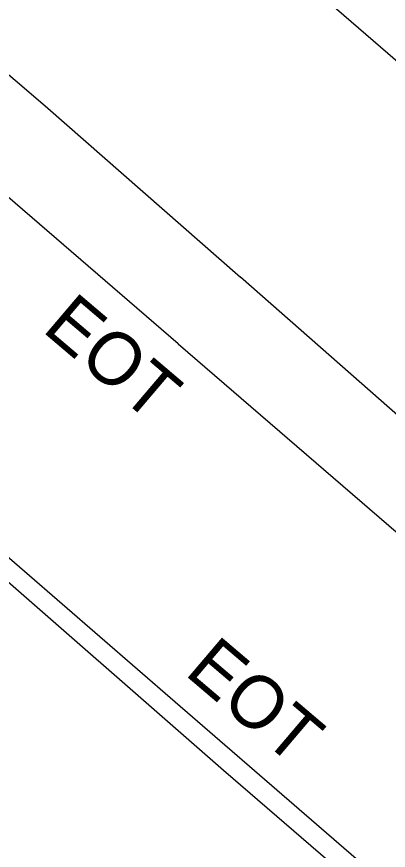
# Model space of a CAD drawing. Extents: x 2076109 to 2080761, y 592812 to 596750.
# Drawn here: x 2076795.1 to 2076830.5, y 596247.5 to 596326.7 of the extents above; entities that cross this region are included whole.
import ezdxf

# ---------------------------------------------------------------- set-up
doc = ezdxf.new("R2010")
doc.units = 0
for name, color, linetype in [('RD_EX_Fence_ChLk', 7, 'Continuous'), ('RD_EX_Misc', 7, 'Continuous'), ('RD_EX_Misc_txCode', 7, 'Continuous'), ('RD_EX_Road', 7, 'Continuous')]:
    doc.layers.add(name, color=color, linetype=linetype)

msp = doc.modelspace()

# ---------------------------------------------------------------- linework, layer by layer
at = {"layer": 'RD_EX_Fence_ChLk'}
msp.add_lwpolyline([(2076822.972, 596329.732), (2076907.019, 596257.073), (2076948.272, 596221.629), (2077023.379, 596156.571), (2077092.731, 596094.038)], dxfattribs=at)
msp.add_lwpolyline([(2076822.972, 596329.732), (2076907.019, 596257.073), (2076948.272, 596221.629), (2077023.379, 596156.571), (2077092.731, 596094.038)], dxfattribs=at)
at = {"layer": 'RD_EX_Misc'}
for points in [[(2076810.466, 596295.642), (2076777.154, 596324.358), (2076741.647, 596354.967), (2076702.034, 596388.717), (2076677.401, 596409.971), (2076647.315, 596435.894), (2076621.027, 596458.583), (2076590.117, 596485.04), (2076559.728, 596511.073), (2076528.183, 596538.3), (2076511.922, 596552.279), (2076473.053, 596585.805), (2076454.386, 596601.838), (2076432.84, 596620.26), (2076409.879, 596640.05), (2076391.022, 596656.418), (2076366.246, 596677.712), (2076342.594, 596698.155), (2076317.697, 596719.663), (2076298.567, 596736.157), (2076283.823, 596748.946)], [(2076810.466, 596295.642), (2076861.804, 596251.392), (2076900.569, 596218.064), (2076940.756, 596183.48), (2076983.389, 596147.001), (2077038.073, 596099.907), (2077086.972, 596057.778), (2077132.275, 596018.797), (2077181.847, 595976.05), (2077229.693, 595934.908), (2077274.19, 595896.66), (2077329.202, 595849.517), (2077358.599, 595824.219)], [(2076810.466, 596295.642), (2076861.804, 596251.392), (2076900.569, 596218.064), (2076940.756, 596183.48), (2076983.389, 596147.001), (2077038.073, 596099.907), (2077086.972, 596057.778), (2077132.275, 596018.797), (2077181.847, 595976.05), (2077229.693, 595934.908), (2077274.19, 595896.66), (2077329.202, 595849.517), (2077358.599, 595824.219)], [(2077334.925, 595810.962), (2077327.547, 595817.304), (2077300.531, 595840.367), (2077267.756, 595868.372), (2077240.066, 595892.053), (2077211.409, 595916.603), (2077178.431, 595944.966), (2077142.263, 595976.086), (2077108.469, 596005.28), (2077069.235, 596038.869), (2077039.155, 596064.675), (2077006.349, 596092.753), (2076967.206, 596126.449), (2076935.593, 596153.651), (2076905.142, 596179.726), (2076872.007, 596208.175), (2076841.3, 596234.653), (2076810.183, 596261.571), (2076792.251, 596277.094)], [(2077334.925, 595810.962), (2077327.547, 595817.304), (2077300.531, 595840.367), (2077267.756, 595868.372), (2077240.066, 595892.053), (2077211.409, 595916.603), (2077178.431, 595944.966), (2077142.263, 595976.086), (2077108.469, 596005.28), (2077069.235, 596038.869), (2077039.155, 596064.675), (2077006.349, 596092.753), (2076967.206, 596126.449), (2076935.593, 596153.651), (2076905.142, 596179.726), (2076872.007, 596208.175), (2076841.3, 596234.653), (2076810.183, 596261.571), (2076792.251, 596277.094)]]:
    msp.add_lwpolyline(points, dxfattribs=at)
at = {"layer": 'RD_EX_Road'}
for points in [[(2076295.807, 596750.034), (2076327.331, 596722.936), (2076360.431, 596694.098), (2076392.102, 596666.863), (2076422.239, 596640.73), (2076455.241, 596612.561), (2076486.01, 596586.14), (2076511.218, 596564.367), (2076545.634, 596535.19), (2076573.693, 596510.932), (2076594.173, 596493.793), (2076616.524, 596474.152), (2076639.677, 596454.591), (2076664.735, 596432.372), (2076686.112, 596413.804), (2076717.685, 596386.955), (2076745.584, 596362.767), (2076775.649, 596337.235), (2076797.834, 596318.25), (2076816.414, 596301.987)], [(2077309.592, 595877.223), (2077282.743, 595900.374), (2077256.364, 595923.264), (2077227.255, 595948.475), (2077198.785, 595972.866), (2077175.799, 595992.64), (2077153.365, 596012.36), (2077130.636, 596031.731), (2077105.618, 596053.51), (2077080.494, 596075.056), (2077051.539, 596099.906), (2077024.399, 596123.257), (2077002.193, 596142.322), (2076978.911, 596162.671), (2076952.209, 596185.236), (2076929.194, 596204.759), (2076902.686, 596227.389), (2076879.244, 596247.551), (2076859.099, 596264.863), (2076833.455, 596286.99), (2076816.414, 596301.987)], [(2077309.592, 595877.223), (2077282.743, 595900.374), (2077256.364, 595923.264), (2077227.255, 595948.475), (2077198.785, 595972.866), (2077175.799, 595992.64), (2077153.365, 596012.36), (2077130.636, 596031.731), (2077105.618, 596053.51), (2077080.494, 596075.056), (2077051.539, 596099.906), (2077024.399, 596123.257), (2077002.193, 596142.322), (2076978.911, 596162.671), (2076952.209, 596185.236), (2076929.194, 596204.759), (2076902.686, 596227.389), (2076879.244, 596247.551), (2076859.099, 596264.863), (2076833.455, 596286.99), (2076816.414, 596301.987)], [(2076790.956, 596275.936), (2076814.772, 596255.118), (2076842.21, 596231.466), (2076870.294, 596207.219), (2076894.792, 596186.021), (2076920.294, 596164.107), (2076947.36, 596141.049), (2076969.166, 596122.001), (2076994.722, 596100.042), (2077020.611, 596077.66), (2077049.576, 596053.31), (2077078.663, 596028.072), (2077094.193, 596014.498), (2077117.898, 595994.159), (2077143.783, 595971.827), (2077167.124, 595951.982), (2077186.93, 595934.866), (2077205.774, 595918.844), (2077227.43, 595900.108), (2077245.338, 595884.558), (2077262.975, 595869.286), (2077283.522, 595851.632), (2077302.454, 595835.443)], [(2076790.956, 596275.936), (2076814.772, 596255.118), (2076842.21, 596231.466), (2076870.294, 596207.219), (2076894.792, 596186.021), (2076920.294, 596164.107), (2076947.36, 596141.049), (2076969.166, 596122.001), (2076994.722, 596100.042), (2077020.611, 596077.66), (2077049.576, 596053.31), (2077078.663, 596028.072), (2077094.193, 596014.498), (2077117.898, 595994.159), (2077143.783, 595971.827), (2077167.124, 595951.982), (2077186.93, 595934.866), (2077205.774, 595918.844), (2077227.43, 595900.108), (2077245.338, 595884.558), (2077262.975, 595869.286), (2077283.522, 595851.632), (2077302.454, 595835.443)]]:
    msp.add_lwpolyline(points, dxfattribs=at)

# ---------------------------------------------------------------- texts
at = {"layer": 'RD_EX_Misc_txCode'}
for p in [(2076797.443, 596296.901), (2076797.443, 596296.901), (2076810.98, 596264.267), (2076810.98, 596264.267)]:
    msp.add_text('EOT', height=5, rotation=319.62738, dxfattribs=at).set_placement(p)

doc.saveas('drawing.dxf')
